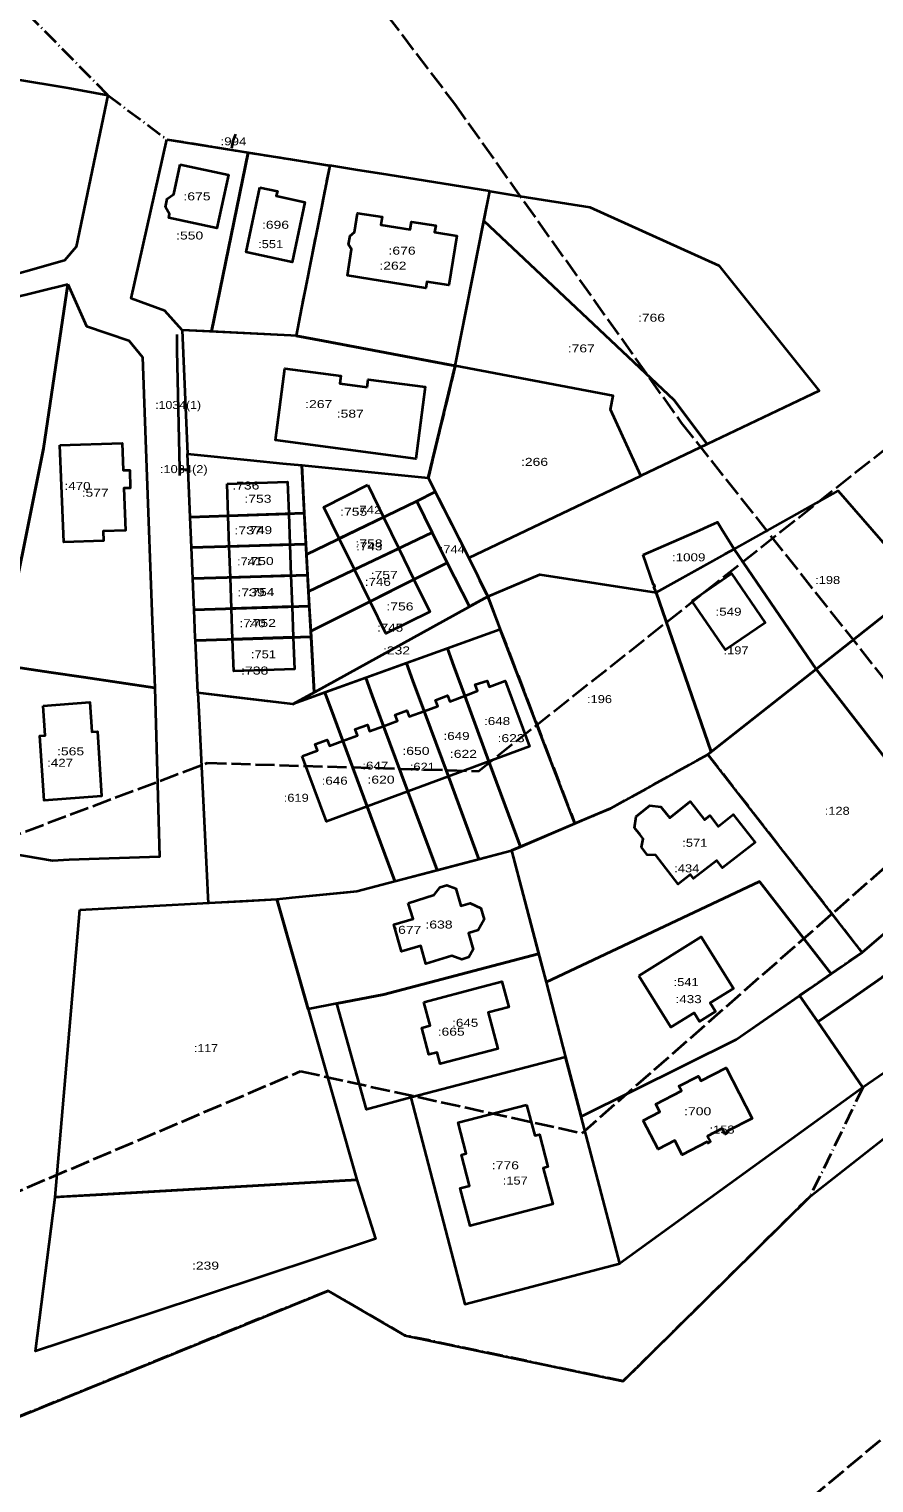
# Model space of a CAD drawing. Extents: x 1185507 to 1197690, y 352608 to 375774.
# Drawn here: x 1190907.1 to 1191065.5, y 364221.4 to 364493.9 of the extents above; entities that cross this region are included whole.
import ezdxf
from ezdxf.enums import TextEntityAlignment as Align

# ---------------------------------------------------------------- set-up
doc = ezdxf.new("R2010")
doc.units = 0
doc.header["$LTSCALE"] = 0.6
doc.linetypes.add('DOT_DASHED', pattern=[7.7, 5, -1.2, 0.3, -1.2])
doc.linetypes.add('LONG_DASHED', pattern=[7.5, 6, -1.5])
for name, color, linetype, lineweight in [('2', 7, 'Continuous', 35), ('4', 7, 'Continuous', 35), ('5', 7, 'DOT_DASHED', 35), ('7', 7, 'LONG_DASHED', 35), ('8', 7, 'Continuous', 35)]:
    doc.layers.add(name, color=color, linetype=linetype, lineweight=lineweight)

msp = doc.modelspace()

# ---------------------------------------------------------------- linework, layer by layer
at = {"layer": '2'}
for points in [[(1190881.57, 364488.28), (1190914.8, 364482.77), (1190921.92, 364481.47), (1190915.94, 364453.04), (1190913.8, 364450.48), (1190898.8, 364446.24), (1190893.57, 364442.12), (1190886.29, 364443.64), (1190873.92, 364445.64)], [(1190932.98, 364473.2), (1190948.22, 364470.74), (1190941.36, 364437.17), (1190935.83, 364437.43), (1190932.6, 364441.06), (1190926.26, 364443.36)], [(1190948.22, 364470.74), (1190963.48, 364468.29), (1190958.2, 364441.61), (1190957.18, 364436.41), (1190956.19, 364436.46), (1190941.36, 364437.17)], [(1190963.48, 364468.29), (1190958.2, 364441.61), (1190957.18, 364436.41), (1190962.23, 364435.46), (1190987.02, 364430.77), (1190993.48, 364463.48), (1190974.41, 364466.54), (1190968.36, 364467.52)], [(1190992.38, 364457.92), (1190993.48, 364463.48), (1190999.14, 364462.57), (1191012.22, 364460.47), (1191036.44, 364449.59), (1191055.19, 364426.06), (1191034.25, 364416.08), (1191028.05, 364424.31)], [(1190992.38, 364457.92), (1191028.05, 364424.31), (1191034.25, 364416.08), (1191021.79, 364410.14), (1191016.1, 364422.57), (1191016.62, 364425.17), (1190987.02, 364430.77)], [(1190914.39, 364446.09), (1190909.87, 364415.25), (1190901.75, 364374.72), (1190874.57, 364378.76), (1190889.75, 364418.95), (1190897.19, 364438.67), (1190903.51, 364443.35)], [(1190914.39, 364446.09), (1190917.9, 364438.19), (1190925.84, 364435.48), (1190928.4, 364432.38), (1190929.16, 364411.7), (1190930.24, 364382.97), (1190930.46, 364376.9), (1190930.71, 364370.41), (1190917.36, 364372.4), (1190911.27, 364373.3), (1190901.75, 364374.72), (1190909.87, 364415.25)], [(1190935.83, 364437.43), (1190936.83, 364414.26), (1190948.64, 364413.08), (1190954.69, 364412.48), (1190958.23, 364412.13), (1190981.96, 364409.77), (1190987.02, 364430.77), (1190962.23, 364435.46), (1190957.18, 364436.41), (1190956.19, 364436.46)], [(1190987.02, 364430.77), (1190981.96, 364409.77), (1190989.54, 364394.76), (1191021.79, 364410.14), (1191016.1, 364422.57), (1191016.62, 364425.17)], [(1190936.83, 364414.26), (1190948.64, 364413.08), (1190954.69, 364412.48), (1190958.23, 364412.13), (1190958.72, 364403.13), (1190937.34, 364402.4)], [(1190958.23, 364412.13), (1190981.96, 364409.77), (1190983.28, 364407.15), (1190979.8, 364405.38), (1190959.14, 364395.43)], [(1191039.26, 364396.43), (1191058.75, 364407.31), (1191074.35, 364389.49), (1191054.62, 364373.93)], [(1190959.14, 364395.43), (1190979.8, 364405.38), (1190982.66, 364399.5), (1190959.52, 364388.47)], [(1190979.8, 364405.38), (1190983.28, 364407.15), (1190989.54, 364394.76), (1190993.1, 364387.51), (1190989.69, 364385.63), (1190985.48, 364393.84), (1190982.66, 364399.5)], [(1190937.34, 364402.4), (1190958.72, 364403.13), (1190959.03, 364397.35), (1190937.59, 364396.7)], [(1190959.52, 364388.47), (1190982.66, 364399.5), (1190985.48, 364393.84), (1190959.93, 364381.04)], [(1191022.26, 364395.35), (1191031.83, 364399.51), (1191032.86, 364399.98), (1191034.33, 364400.66), (1191036.15, 364401.49), (1191036.92, 364400.24), (1191039.26, 364396.43), (1191038.47, 364395.99), (1191037.52, 364395.46), (1191034.99, 364394.05), (1191024.66, 364388.27), (1191024.25, 364389.35), (1191024.42, 364389.4), (1191024.31, 364389.79), (1191024.16, 364389.74)], [(1190937.59, 364396.7), (1190959.03, 364397.35), (1190959.35, 364391.56), (1190937.83, 364390.89)], [(1191024.66, 364388.27), (1191039.26, 364396.43), (1191054.62, 364373.93), (1191035, 364358.45)], [(1190959.93, 364381.04), (1190985.48, 364393.84), (1190989.69, 364385.63), (1190963.51, 364371.18), (1190960.55, 364369.55)], [(1190937.83, 364390.89), (1190959.35, 364391.56), (1190959.66, 364385.74), (1190938.07, 364385.04), (1190937.96, 364387.84)], [(1190993.1, 364387.51), (1191002.85, 364391.63), (1191024.66, 364388.27), (1191035, 364358.45), (1191034.36, 364357.93), (1191016.1, 364347.82), (1191009.43, 364344.98)], [(1191054.62, 364373.93), (1191074.35, 364389.49), (1191103.89, 364355.73), (1191082.83, 364337.64)], [(1190938.07, 364385.04), (1190959.66, 364385.74), (1190959.98, 364379.98), (1190938.33, 364379.28), (1190938.3, 364379.76)], [(1190956.55, 364367.33), (1190993.1, 364387.51), (1190995.46, 364381.35)], [(1190938.33, 364379.28), (1190959.98, 364379.98), (1190960.55, 364369.55), (1190956.55, 364367.33), (1190938.75, 364369.45)], [(1190995.46, 364381.35), (1190985.53, 364377.77), (1190986.73, 364374.48), (1190988.78, 364368.93), (1190993.32, 364356.63), (1190999.22, 364340.62), (1191009.43, 364344.98)], [(1190977.87, 364375.01), (1190979.09, 364371.73), (1190981.19, 364366.06), (1190985.72, 364353.82), (1190991.46, 364338.31), (1190997.56, 364339.91), (1190999.22, 364340.62), (1190993.32, 364356.63), (1190988.78, 364368.93), (1190986.73, 364374.48), (1190985.53, 364377.77)], [(1190901.75, 364374.72), (1190911.27, 364373.3), (1190917.36, 364372.4), (1190930.71, 364370.41), (1190931.6, 364338.75), (1190914.65, 364338.2), (1190911.54, 364338.02), (1190894.32, 364340.92), (1190895.36, 364345.65)], [(1190970.24, 364372.26), (1190971.46, 364368.98), (1190973.58, 364363.26), (1190978.12, 364351.01), (1190983.61, 364336.25), (1190991.46, 364338.31), (1190985.72, 364353.82), (1190981.19, 364366.06), (1190979.09, 364371.73), (1190977.87, 364375.01)], [(1190962.6, 364369.51), (1190963.82, 364366.23), (1190965.95, 364360.46), (1190970.49, 364348.19), (1190975.68, 364334.17), (1190983.61, 364336.25), (1190978.12, 364351.01), (1190973.58, 364363.26), (1190971.46, 364368.98), (1190970.24, 364372.26)], [(1191034.36, 364357.93), (1191054.62, 364373.93), (1191082.83, 364337.64), (1191063.25, 364320.81)], [(1190938.75, 364369.45), (1190938.93, 364365.9), (1190940.44, 364335.17), (1190940.63, 364331.18), (1190940.69, 364330.11), (1190947.15, 364330.46), (1190953.6, 364330.81), (1190956.46, 364331.1), (1190966.79, 364332.12), (1190968.54, 364332.29), (1190975.68, 364334.17), (1190970.49, 364348.19), (1190965.95, 364360.46), (1190963.82, 364366.23), (1190962.6, 364369.51), (1190956.55, 364367.33), (1190951.74, 364367.9), (1190944.8, 364368.73)], [(1191051.54, 364312.74), (1191057.47, 364316.83), (1191063.25, 364320.81), (1191082.83, 364337.64), (1191103.89, 364355.73), (1191107.14, 364358.5), (1191111.04, 364353.95), (1191086.74, 364333.09), (1191066.92, 364316.05), (1191060.88, 364311.89), (1191054.94, 364307.8)], [(1190997.56, 364339.91), (1191004.02, 364315.25), (1191044.03, 364334.09), (1191057.47, 364316.83), (1191063.25, 364320.81), (1191034.36, 364357.93), (1191016.1, 364347.82)], [(1190953.6, 364330.81), (1190956.46, 364331.1), (1190968.54, 364332.29), (1190997.56, 364339.91), (1191002.63, 364320.56), (1190973.61, 364312.96), (1190964.79, 364311.24), (1190959.46, 364310.21)], [(1191004.02, 364315.25), (1191007.7, 364301.22), (1191010.62, 364290.06), (1191039.63, 364304.53), (1191057.47, 364316.83), (1191044.03, 364334.09)], [(1191054.94, 364307.8), (1191060.88, 364311.89), (1191066.92, 364316.05), (1191085.93, 364332.39), (1191095.59, 364321.14), (1191075.38, 364303.78), (1191063.4, 364295.53)], [(1190916.66, 364328.78), (1190953.6, 364330.81), (1190968.56, 364278.2), (1190912.05, 364274.98)], [(1190964.79, 364311.24), (1190973.61, 364312.96), (1191002.63, 364320.56), (1191004.02, 364315.25), (1191007.7, 364301.22), (1190978.68, 364293.61), (1190970.35, 364291.39)], [(1191010.62, 364290.06), (1191039.63, 364304.53), (1191051.54, 364312.74), (1191054.94, 364307.8), (1191063.4, 364295.53), (1191017.84, 364262.53)], [(1191007.7, 364301.22), (1190978.68, 364293.61), (1190988.82, 364254.92), (1191017.84, 364262.53), (1191010.62, 364290.06)], [(1190912.05, 364274.98), (1190913.71, 364275.07), (1190920.9, 364275.48), (1190968.56, 364278.2), (1190972.07, 364267.15), (1190929.85, 364253.18), (1190924.11, 364251.28), (1190908.35, 364246.07)]]:
    msp.add_lwpolyline(points, close=True, dxfattribs=at)
at = {"layer": '4'}
msp.add_lwpolyline([(1190647.14, 364349.43), (1190692.88, 364324.17), (1190757.05, 364287.63), (1190847.4, 364236.46), (1190870.47, 364225.86), (1190887.93, 364229.43), (1190903.2, 364233), (1190963.17, 364257.43), (1190977.58, 364249.06), (1191018.45, 364240.46), (1191053.56, 364275.17), (1191077.75, 364294.16)], dxfattribs=at)
at = {"layer": '5'}
for points in [[(1190897.07, 364506.7), (1190921.92, 364481.47), (1190932.98, 364473.2), (1190963.48, 364468.29), (1190958.2, 364441.61), (1190957.18, 364436.41), (1190962.23, 364435.46), (1190987.02, 364430.77), (1190981.96, 364409.77), (1190989.54, 364394.76), (1190993.1, 364387.51), (1190995.46, 364381.35), (1191009.43, 364344.98), (1191016.1, 364347.82), (1191034.36, 364357.93), (1191063.25, 364320.81), (1191057.47, 364316.83), (1191051.54, 364312.74), (1191063.4, 364295.53), (1191053.56, 364275.17), (1191018.45, 364240.46), (1190977.58, 364249.06)], [(1190977.58, 364249.06), (1190963.17, 364257.43), (1190903.2, 364233), (1190887.93, 364229.43), (1190870.47, 364225.86), (1190847.4, 364236.46), (1190757.05, 364287.63), (1190692.88, 364324.17), (1190647.14, 364349.43), (1190632.21, 364356.82), (1190626.4, 364363.08), (1190622.19, 364369.01), (1190611.28, 364369.51), (1190595.22, 364367.23), (1190532.29, 364357.36), (1190463.09, 364355.18), (1190404.66, 364360.8), (1190352.99, 364368.35)]]:
    msp.add_lwpolyline(points, dxfattribs=at)
at = {"layer": '7'}
for points in [[(1192415.6, 364440.24), (1191866.38, 364672.34), (1191840.46, 364707.47), (1191734.83, 364812.28), (1191719.9, 364840.01), (1191472.73, 364953.87), (1191341.42, 364915.36), (1191218, 364742.83), (1191294.12, 364597.33), (1191343, 364505.77), (1191359.36, 364477.47), (1191352.83, 364440.49), (1191325.5, 364415.55), (1191208.53, 364347.34), (1191030.05, 364198.94), (1190997.05, 364201.53), (1190961.38, 364212.57), (1190883.65, 364181.63), (1190850.92, 364187.77), (1190612.74, 364326.54)], [(1190707.81, 364806.99), (1190755.97, 364752.73), (1190803.32, 364700.36), (1190853.99, 364642.05), (1190904.39, 364585.81), (1190949.74, 364528.69), (1190986.85, 364479.88), (1191029.36, 364420.09), (1191080.38, 364355.61), (1191108.52, 364323.42), (1191113.15, 364318.21), (1191165.71, 364272.75), (1191200.61, 364247.27), (1191243.79, 364215.31), (1191253.26, 364208.29), (1191308.88, 364168.98), (1191331.76, 364151.65), (1191338.46, 364129.1), (1191340.09, 364070.88), (1191344.3, 363990.8)], [(1189191.9, 364549.27), (1189395.22, 364588.56), (1189548.85, 364595.13), (1189680.04, 364579.91), (1189784.57, 364598.37), (1189872.95, 364591.01), (1190232.66, 364472.66), (1190283.77, 364463.98), (1190368.24, 364469.75), (1190452.8, 364459.37), (1190615.51, 364473.08), (1190678.91, 364456.96), (1190881.18, 364333.99), (1190940.56, 364356.34), (1190991.35, 364354.82), (1191177.32, 364502.05)], [(1189181.53, 364482.48), (1189344.66, 364521.04), (1189504.15, 364533.94), (1189608.74, 364531.21), (1189675.93, 364518.82), (1189812.58, 364539.7), (1189922.37, 364516.11), (1190113.06, 364450.97), (1190189.38, 364420.33), (1190281.14, 364404.98), (1190362.32, 364410.03), (1190480.68, 364396.9), (1190633.76, 364412.12), (1190877.81, 364264.44), (1190958.03, 364298.57), (1191010.79, 364286.96), (1191124.41, 364386.71)]]:
    msp.add_lwpolyline(points, dxfattribs=at)
at = {"layer": '8'}
msp.add_line((1190935.33, 364411.47), (1190936.94, 364411.34), dxfattribs=at)
for points in [[(1190945.84, 364474.15), (1190945.33, 364472.94), (1190945.06, 364471.53)], [(1190934.83, 364436.63), (1190934.86, 364433.61), (1190935.33, 364411.47), (1190935.31, 364410.23)]]:
    msp.add_lwpolyline(points, dxfattribs=at)
for points in [[(1190935.45, 364468.49), (1190944.5, 364466.56), (1190942.35, 364456.56), (1190933.33, 364458.47), (1190933.47, 364459.18), (1190932.73, 364460.5), (1190933.05, 364462.06), (1190934.29, 364462.96)], [(1190950.37, 364464.21), (1190953.67, 364463.52), (1190953.48, 364462.62), (1190958.83, 364461.44), (1190956.44, 364450.19), (1190947.82, 364452.09)], [(1190967.29, 364455.1), (1190968.11, 364455.8), (1190968.68, 364459.39), (1190973.3, 364458.66), (1190973.06, 364457.17), (1190978.57, 364456.3), (1190978.81, 364457.78), (1190983.35, 364457.06), (1190983.15, 364455.81), (1190987.29, 364455.15), (1190985.78, 364445.87), (1190981.67, 364446.51), (1190981.48, 364445.31), (1190966.8, 364447.7), (1190967.6, 364452.63), (1190967.01, 364453.48)], [(1190970.5, 364426.78), (1190970.69, 364428.2), (1190981.38, 364426.8), (1190979.61, 364413.35), (1190953.3, 364416.8), (1190955.07, 364430.25), (1190965.59, 364428.87), (1190965.4, 364427.45)], [(1190912.93, 364415.87), (1190924.6, 364416.26), (1190924.8, 364411.19), (1190926, 364411.19), (1190926.12, 364407.82), (1190924.92, 364407.82), (1190925.22, 364399.92), (1190921.04, 364399.75), (1190921.11, 364397.96), (1190913.64, 364397.71)], [(1190944.26, 364408.64), (1190955.59, 364409.05), (1190955.81, 364403.04), (1190944.47, 364402.65)], [(1190970.62, 364408.44), (1190973.58, 364402.39), (1190965.28, 364398.39), (1190962.38, 364404.29)], [(1190944.47, 364402.64), (1190955.81, 364403.03), (1190956.01, 364397.26), (1190944.67, 364396.92)], [(1190973.58, 364402.38), (1190976.44, 364396.54), (1190968.14, 364392.58), (1190965.28, 364398.38)], [(1190944.67, 364396.91), (1190956.01, 364397.25), (1190956.22, 364391.47), (1190944.87, 364391.11)], [(1190976.44, 364396.53), (1190979.27, 364390.73), (1190971.06, 364386.62), (1190968.13, 364392.57)], [(1190944.87, 364391.1), (1190956.22, 364391.46), (1190956.43, 364385.64), (1190945.08, 364385.27)], [(1191031.36, 364386.73), (1191038.76, 364391.84), (1191045.08, 364382.61), (1191037.67, 364377.53)], [(1190979.27, 364390.72), (1190982.24, 364384.65), (1190974.01, 364380.62), (1190971.06, 364386.61)], [(1190945.08, 364385.26), (1190956.43, 364385.63), (1190956.64, 364379.88), (1190945.28, 364379.51)], [(1190945.28, 364379.5), (1190956.64, 364379.87), (1190956.86, 364373.94), (1190945.49, 364373.53)], [(1190988.78, 364368.93), (1190991.16, 364369.84), (1190990.77, 364371.02), (1190992.98, 364371.75), (1190993.37, 364370.58), (1190996.39, 364371.73), (1191000.93, 364359.44), (1190993.32, 364356.63)], [(1190909.79, 364367.05), (1190918.5, 364367.75), (1190918.88, 364362.14), (1190919.97, 364362.22), (1190920.71, 364350.1), (1190909.95, 364349.29), (1190909.14, 364361.4), (1190910.16, 364361.48)], [(1190981.19, 364366.06), (1190983.72, 364366.98), (1190983.29, 364368.1), (1190985.53, 364368.97), (1190985.97, 364367.86), (1190988.78, 364368.93), (1190993.32, 364356.63), (1190985.72, 364353.82)], [(1190973.58, 364363.26), (1190976.18, 364364.22), (1190975.75, 364365.35), (1190977.95, 364366.18), (1190978.38, 364365.04), (1190981.19, 364366.06), (1190985.72, 364353.82), (1190978.12, 364351.01)], [(1190965.95, 364360.46), (1190968.68, 364361.48), (1190968.26, 364362.64), (1190970.56, 364363.47), (1190970.97, 364362.3), (1190973.58, 364363.26), (1190978.12, 364351.01), (1190970.49, 364348.19)], [(1190958.33, 364357.63), (1190961.2, 364358.69), (1190960.78, 364359.83), (1190963.01, 364360.65), (1190963.43, 364359.52), (1190965.95, 364360.46), (1190970.49, 364348.19), (1190962.86, 364345.37)], [(1191020.62, 364344.16), (1191020.9, 364346.31), (1191023.48, 364348.35), (1191025.57, 364348.12), (1191026.6, 364346.82), (1191027.22, 364346.04), (1191031.06, 364349.09), (1191033.73, 364345.69), (1191034.72, 364346.46), (1191036.27, 364344.45), (1191039.11, 364346.67), (1191043.19, 364341.43), (1191037.09, 364336.69), (1191036.02, 364338.07), (1191031.66, 364334.68), (1191031.07, 364335.44), (1191028.76, 364333.65), (1191024.61, 364339.03), (1191023.01, 364339.12), (1191021.91, 364340.55), (1191022.22, 364342.12), (1191021.64, 364342.88)], [(1190978.2, 364330.06), (1190983.08, 364331.64), (1190984.18, 364333.06), (1190985.44, 364333.42), (1190987.15, 364332.8), (1190988.06, 364329.53), (1190989.82, 364330.06), (1190991.81, 364329.14), (1190992.44, 364327.01), (1190991.32, 364325.01), (1190989.47, 364324.46), (1190990.34, 364321.35), (1190989.56, 364319.94), (1190988.26, 364319.5), (1190986.38, 364320.16), (1190981.52, 364318.69), (1190980.55, 364322.07), (1190976.96, 364321.03), (1190975.5, 364326.06), (1190979.11, 364327.1)], [(1191021.41, 364316.46), (1191027.44, 364306.79), (1191031.81, 364309.51), (1191032.81, 364307.9), (1191035.78, 364309.74), (1191034.78, 364311.36), (1191039.15, 364314.09), (1191033.12, 364323.76)], [(1190981.14, 364311.49), (1190991.93, 364314.35), (1190995.77, 364315.36), (1190997.03, 364310.59), (1190993.2, 364309.57), (1190994.99, 364302.77), (1190984.2, 364299.92), (1190983.62, 364302.1), (1190982.07, 364301.69), (1190980.74, 364306.7), (1190982.3, 364307.12)], [(1191022.24, 364289.35), (1191025.35, 364290.96), (1191024.6, 364292.4), (1191029.4, 364294.88), (1191028.94, 364295.77), (1191032.6, 364297.66), (1191033.06, 364296.77), (1191037.76, 364299.2), (1191042.66, 364289.71), (1191037.99, 364287.3), (1191038.11, 364287.07), (1191037.58, 364286.79), (1191037.04, 364287.83), (1191034.29, 364286.41), (1191034.83, 364285.37), (1191034.32, 364285.11), (1191034.2, 364285.34), (1191029.51, 364282.91), (1191028.14, 364285.55), (1191025.03, 364283.95)], [(1191000.39, 364292.29), (1191001.91, 364286.49), (1191002.78, 364286.71), (1191004.37, 364280.64), (1191003.5, 364280.41), (1191005.27, 364273.64), (1190989.79, 364269.58), (1190987.94, 364276.65), (1190989.7, 364277.1), (1190988.18, 364282.88), (1190989.07, 364283.12), (1190987.55, 364288.93)]]:
    msp.add_lwpolyline(points, close=True, dxfattribs=at)

# ---------------------------------------------------------------- texts
at = {"layer": '2'}
for s, width, p in [(':550', 1.3, (1190937.2405, 364454.435)), (':551', 1.2, (1190952.42, 364452.825)), (':262', 1.3, (1190975.3305, 364448.78)), (':766', 1.3, (1191023.7855, 364439.03)), (':767', 1.3, (1191010.6355, 364433.28)), (':267', 1.3, (1190961.4255, 364422.85)), (':266', 1.3, (1191001.8755, 364412.015)), (':470', 1.25, (1190916.2305, 364407.5)), (':736', 1.3, (1190947.7755, 364407.58)), (':742', 1.25, (1190970.7555, 364403.03)), (':737', 1.3, (1190948.1855, 364399.165)), (':743', 1.25, (1190970.9005, 364396.175)), (':744', 1.2, (1190986.45, 364395.64)), (':741', 1.2, (1190948.47, 364393.37)), (':1009', 1.25, (1191030.76, 364394.13)), (':746', 1.25, (1190972.5005, 364389.52)), (':198', 1.2, (1191056.805, 364389.87)), (':739', 1.3, (1190948.7455, 364387.55)), (':740', 1.25, (1190949.0255, 364381.76)), (':745', 1.25, (1190974.8105, 364380.945)), (':232', 1.3, (1190976.0055, 364376.67)), (':197', 1.2, (1191039.64, 364376.69)), (':738', 1.3, (1190949.4405, 364372.905)), (':196', 1.2, (1191014.05, 364367.555)), (':623', 1.3, (1190997.4805, 364360.235)), (':622', 1.3, (1190988.5455, 364357.29)), (':427', 1.25, (1190912.9605, 364355.62)), (':621', 1.2, (1190980.85, 364354.88)), (':620', 1.3, (1190973.1055, 364352.465)), (':619', 1.2, (1190957.215, 364349.06)), (':128', 1.2, (1191058.595, 364346.62)), (':434', 1.2, (1191030.405, 364335.84)), (':677', 1.3, (1190978.1155, 364324.31)), (':433', 1.25, (1191030.7455, 364311.325)), (':665', 1.3, (1190986.2455, 364305.225)), (':117', 1.15, (1190940.3045, 364302.145)), (':158', 1.2, (1191037.01, 364286.885)), (':157', 1.2, (1190998.26, 364277.32)), (':239', 1.3, (1190940.2105, 364261.385))]:
    msp.add_text(s, height=1.5, dxfattribs=dict(at, width=width)).set_placement(p, align=Align.CENTER)
at = {"layer": '8'}
for s, width, p in [(':994', 1.25, (1190945.4505, 364472.09)), (':675', 1.3, (1190938.6155, 364461.775)), (':696', 1.3, (1190953.3255, 364456.45)), (':676', 1.3, (1190977.0455, 364451.6)), (':1034(1)', 1.15, (1190935.08, 364422.68)), (':587', 1.3, (1190967.3405, 364421.05)), (':1034(2)', 1.2, (1190936.1355, 364410.655)), (':577', 1.3, (1190919.5255, 364406.235)), (':753', 1.3, (1190950.0355, 364405.1)), (':755', 1.3, (1190967.9805, 364402.665)), (':749', 1.25, (1190950.2405, 364399.225)), (':758', 1.3, (1190970.8605, 364396.73)), (':750', 1.3, (1190950.4455, 364393.43)), (':757', 1.3, (1190973.7005, 364390.825)), (':754', 1.25, (1190950.6505, 364387.615)), (':756', 1.3, (1190976.6505, 364384.92)), (':549', 1.25, (1191038.2205, 364383.935)), (':752', 1.3, (1190950.8605, 364381.82)), (':751', 1.2, (1190951.07, 364375.95)), (':648', 1.25, (1190994.8555, 364363.44)), (':649', 1.25, (1190987.2555, 364360.645)), (':565', 1.3, (1190914.9255, 364357.77)), (':650', 1.3, (1190979.6505, 364357.845)), (':647', 1.25, (1190972.0355, 364355.08)), (':646', 1.25, (1190964.4105, 364352.26)), (':571', 1.2, (1191031.905, 364340.62)), (':638', 1.3, (1190983.9705, 364325.305)), (':541', 1.2, (1191030.28, 364314.525)), (':645', 1.25, (1190988.8855, 364306.89)), (':700', 1.3, (1191032.4505, 364290.305)), (':776', 1.3, (1190996.4105, 364280.185))]:
    msp.add_text(s, height=1.5, dxfattribs=dict(at, width=width)).set_placement(p, align=Align.CENTER)

doc.saveas('drawing.dxf')
